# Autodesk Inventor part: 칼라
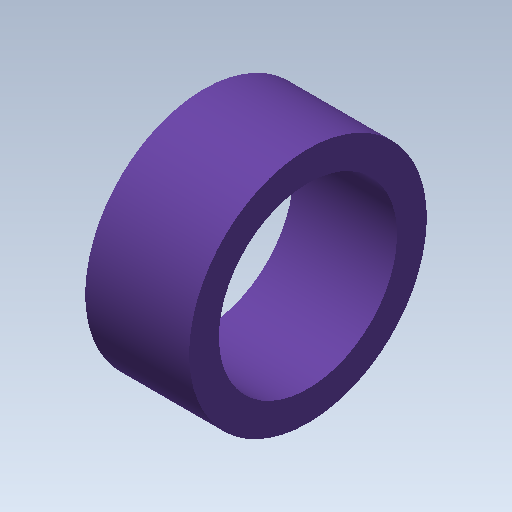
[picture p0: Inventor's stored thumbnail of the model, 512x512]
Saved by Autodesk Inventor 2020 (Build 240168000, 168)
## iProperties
Created: 2020-04
Part Number: 칼라
Material: 강철, 연강
Document SubType Name: Modeling
Designer: mduedu
Density: 7.86 g/cm^3
Mass: 4.83981 g
Surface Area: 7.91681 cm^2
Volume: 0.615752 cm^3
Appearance: 보라색
Author: mduedu
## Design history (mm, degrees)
sketch "스케치1"
  geometry: C1 r 8 at (0, 0); C2 r 6 at (0, 0); 1 further point
  constraints: 2 centre point, 2 coincident
  dimensions: "d0" = 16 diameter of C1; "d1" = 12 diameter of C2
extrude "돌출1" new body sketch "스케치1" distance "d2" = 7; taper "d3" = 0 deg
node "솔리드1"
